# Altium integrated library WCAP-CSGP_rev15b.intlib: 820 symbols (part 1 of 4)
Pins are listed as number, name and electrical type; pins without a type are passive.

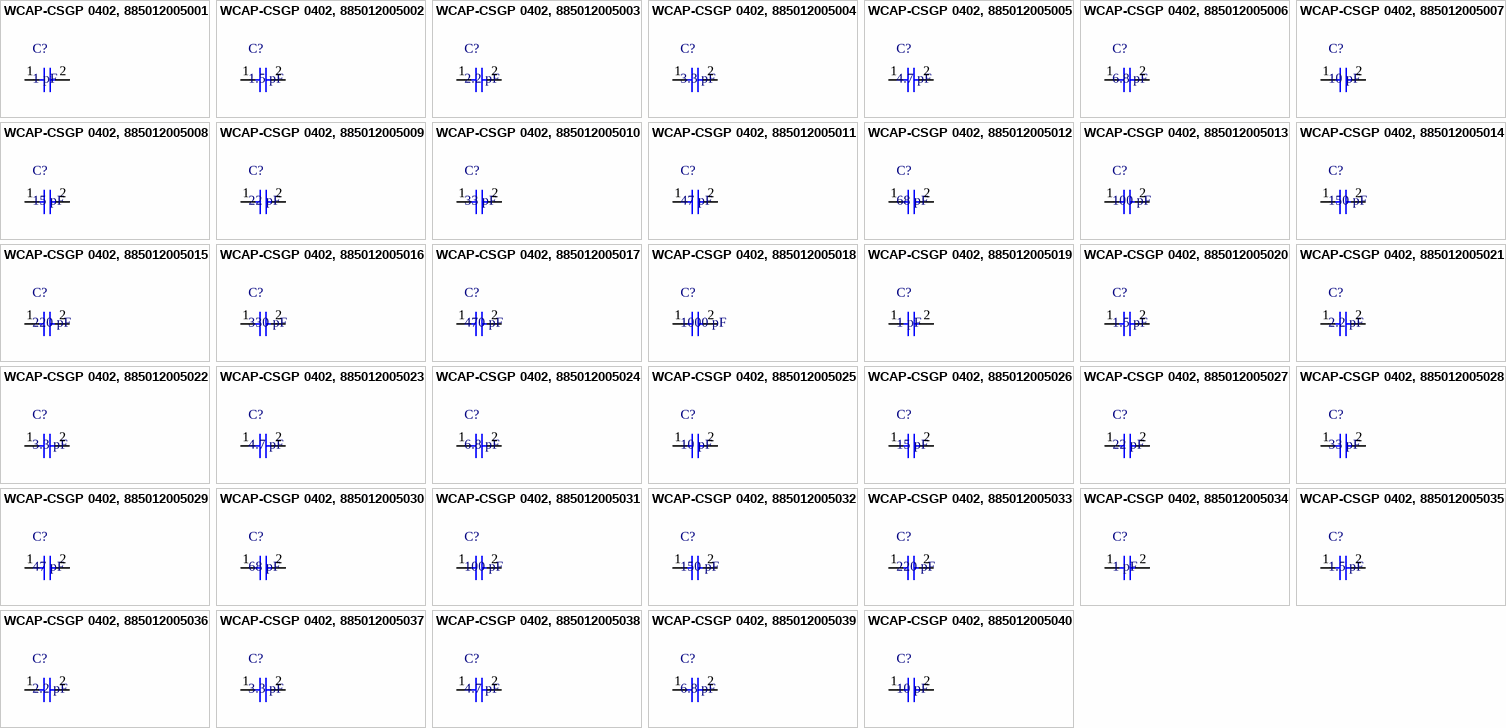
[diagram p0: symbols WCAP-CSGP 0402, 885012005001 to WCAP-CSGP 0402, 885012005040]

## WCAP-CSGP 0402, 885012005001
designator C?, comment 1 pF
WCAP-CSGP MLCC, NP0, 0402, 1 pF,10Vdc; Manufacturer: Wurth Elektronik; partNo: 885012005001; E-mail: libraries@we-online.com
footprint WCAP-CSGP 0402, H=0.5mm
pins: 1, 2

## WCAP-CSGP 0402, 885012005002
designator C?, comment 1.5 pF
WCAP-CSGP MLCC, NP0, 0402, 1.5 pF,10Vdc; Manufacturer: Wurth Elektronik; partNo: 885012005002; E-mail: libraries@we-online.com
footprint WCAP-CSGP 0402, H=0.5mm
pins: 1, 2

## WCAP-CSGP 0402, 885012005003
designator C?, comment 2.2 pF
WCAP-CSGP MLCC, NP0, 0402, 2.2 pF,10Vdc; Manufacturer: Wurth Elektronik; partNo: 885012005003; E-mail: libraries@we-online.com
footprint WCAP-CSGP 0402, H=0.5mm
pins: 1, 2

## WCAP-CSGP 0402, 885012005004
designator C?, comment 3.3 pF
WCAP-CSGP MLCC, NP0, 0402, 3.3 pF,10Vdc; Manufacturer: Wurth Elektronik; partNo: 885012005004; E-mail: libraries@we-online.com
footprint WCAP-CSGP 0402, H=0.5mm
pins: 1, 2

## WCAP-CSGP 0402, 885012005005
designator C?, comment 4.7 pF
WCAP-CSGP MLCC, NP0, 0402, 4.7 pF,10Vdc; Manufacturer: Wurth Elektronik; partNo: 885012005005; E-mail: libraries@we-online.com
footprint WCAP-CSGP 0402, H=0.5mm
pins: 1, 2

## WCAP-CSGP 0402, 885012005006
designator C?, comment 6.8 pF
WCAP-CSGP MLCC, NP0, 0402, 6.8 pF,10Vdc; Manufacturer: Wurth Elektronik; partNo: 885012005006; E-mail: libraries@we-online.com
footprint WCAP-CSGP 0402, H=0.5mm
pins: 1, 2

## WCAP-CSGP 0402, 885012005007
designator C?, comment 10 pF
WCAP-CSGP MLCC, NP0, 0402, 10 pF,10Vdc; Manufacturer: Wurth Elektronik; partNo: 885012005007; E-mail: libraries@we-online.com
footprint WCAP-CSGP 0402, H=0.5mm
pins: 1, 2

## WCAP-CSGP 0402, 885012005008
designator C?, comment 15 pF
WCAP-CSGP MLCC, NP0, 0402, 15 pF,10Vdc; Manufacturer: Wurth Elektronik; partNo: 885012005008; E-mail: libraries@we-online.com
footprint WCAP-CSGP 0402, H=0.5mm
pins: 1, 2

## WCAP-CSGP 0402, 885012005009
designator C?, comment 22 pF
WCAP-CSGP MLCC, NP0, 0402, 22 pF,10Vdc; Manufacturer: Wurth Elektronik; partNo: 885012005009; E-mail: libraries@we-online.com
footprint WCAP-CSGP 0402, H=0.5mm
pins: 1, 2

## WCAP-CSGP 0402, 885012005010
designator C?, comment 33 pF
WCAP-CSGP MLCC, NP0, 0402, 33 pF,10Vdc; Manufacturer: Wurth Elektronik; partNo: 885012005010; E-mail: libraries@we-online.com
footprint WCAP-CSGP 0402, H=0.5mm
pins: 1, 2

## WCAP-CSGP 0402, 885012005011
designator C?, comment 47 pF
WCAP-CSGP MLCC, NP0, 0402, 47 pF,10Vdc; Manufacturer: Wurth Elektronik; partNo: 885012005011; E-mail: libraries@we-online.com
footprint WCAP-CSGP 0402, H=0.5mm
pins: 1, 2

## WCAP-CSGP 0402, 885012005012
designator C?, comment 68 pF
WCAP-CSGP MLCC, NP0, 0402, 68 pF,10Vdc; Manufacturer: Wurth Elektronik; partNo: 885012005012; E-mail: libraries@we-online.com
footprint WCAP-CSGP 0402, H=0.5mm
pins: 1, 2

## WCAP-CSGP 0402, 885012005013
designator C?, comment 100 pF
WCAP-CSGP MLCC, NP0, 0402, 100 pF,10Vdc; Manufacturer: Wurth Elektronik; partNo: 885012005013; E-mail: libraries@we-online.com
footprint WCAP-CSGP 0402, H=0.5mm
pins: 1, 2

## WCAP-CSGP 0402, 885012005014
designator C?, comment 150 pF
WCAP-CSGP MLCC, NP0, 0402, 150 pF,10Vdc; Manufacturer: Wurth Elektronik; partNo: 885012005014; E-mail: libraries@we-online.com
footprint WCAP-CSGP 0402, H=0.5mm
pins: 1, 2

## WCAP-CSGP 0402, 885012005015
designator C?, comment 220 pF
WCAP-CSGP MLCC, NP0, 0402, 220 pF,10Vdc; Manufacturer: Wurth Elektronik; partNo: 885012005015; E-mail: libraries@we-online.com
footprint WCAP-CSGP 0402, H=0.5mm
pins: 1, 2

## WCAP-CSGP 0402, 885012005016
designator C?, comment 330 pF
WCAP-CSGP MLCC, NP0, 0402, 330 pF,10Vdc; Manufacturer: Wurth Elektronik; partNo: 885012005016; E-mail: libraries@we-online.com
footprint WCAP-CSGP 0402, H=0.5mm
pins: 1, 2

## WCAP-CSGP 0402, 885012005017
designator C?, comment 470 pF
WCAP-CSGP MLCC, NP0, 0402, 470 pF,10Vdc; Manufacturer: Wurth Elektronik; partNo: 885012005017; E-mail: libraries@we-online.com
footprint WCAP-CSGP 0402, H=0.5mm
pins: 1, 2

## WCAP-CSGP 0402, 885012005018
designator C?, comment 1000 pF
WCAP-CSGP MLCC, NP0, 0402, 1000 pF,10Vdc; Manufacturer: Wurth Elektronik; partNo: 885012005018; E-mail: libraries@we-online.com
footprint WCAP-CSGP 0402, H=0.5mm
pins: 1, 2

## WCAP-CSGP 0402, 885012005019
designator C?, comment 1 pF
WCAP-CSGP MLCC, NP0, 0402, 1 pF,16Vdc; Manufacturer: Wurth Elektronik; partNo: 885012005019; E-mail: libraries@we-online.com
footprint WCAP-CSGP 0402, H=0.5mm
pins: 1, 2

## WCAP-CSGP 0402, 885012005020
designator C?, comment 1.5 pF
WCAP-CSGP MLCC, NP0, 0402, 1.5 pF,16Vdc; Manufacturer: Wurth Elektronik; partNo: 885012005020; E-mail: libraries@we-online.com
footprint WCAP-CSGP 0402, H=0.5mm
pins: 1, 2

## WCAP-CSGP 0402, 885012005021
designator C?, comment 2.2 pF
WCAP-CSGP MLCC, NP0, 0402, 2.2 pF,16Vdc; Manufacturer: Wurth Elektronik; partNo: 885012005021; E-mail: libraries@we-online.com
footprint WCAP-CSGP 0402, H=0.5mm
pins: 1, 2

## WCAP-CSGP 0402, 885012005022
designator C?, comment 3.3 pF
WCAP-CSGP MLCC, NP0, 0402, 3.3 pF,16Vdc; Manufacturer: Wurth Elektronik; partNo: 885012005022; E-mail: libraries@we-online.com
footprint WCAP-CSGP 0402, H=0.5mm
pins: 1, 2

## WCAP-CSGP 0402, 885012005023
designator C?, comment 4.7 pF
WCAP-CSGP MLCC, NP0, 0402, 4.7 pF,16Vdc; Manufacturer: Wurth Elektronik; partNo: 885012005023; E-mail: libraries@we-online.com
footprint WCAP-CSGP 0402, H=0.5mm
pins: 1, 2

## WCAP-CSGP 0402, 885012005024
designator C?, comment 6.8 pF
WCAP-CSGP MLCC, NP0, 0402, 6.8 pF,16Vdc; Manufacturer: Wurth Elektronik; partNo: 885012005024; E-mail: libraries@we-online.com
footprint WCAP-CSGP 0402, H=0.5mm
pins: 1, 2

## WCAP-CSGP 0402, 885012005025
designator C?, comment 10 pF
WCAP-CSGP MLCC, NP0, 0402, 10 pF,16Vdc; Manufacturer: Wurth Elektronik; partNo: 885012005025; E-mail: libraries@we-online.com
footprint WCAP-CSGP 0402, H=0.5mm
pins: 1, 2

## WCAP-CSGP 0402, 885012005026
designator C?, comment 15 pF
WCAP-CSGP MLCC, NP0, 0402, 15 pF,16Vdc; Manufacturer: Wurth Elektronik; partNo: 885012005026; E-mail: libraries@we-online.com
footprint WCAP-CSGP 0402, H=0.5mm
pins: 1, 2

## WCAP-CSGP 0402, 885012005027
designator C?, comment 22 pF
WCAP-CSGP MLCC, NP0, 0402, 22 pF,16Vdc; Manufacturer: Wurth Elektronik; partNo: 885012005027; E-mail: libraries@we-online.com
footprint WCAP-CSGP 0402, H=0.5mm
pins: 1, 2

## WCAP-CSGP 0402, 885012005028
designator C?, comment 33 pF
WCAP-CSGP MLCC, NP0, 0402, 33 pF,16Vdc; Manufacturer: Wurth Elektronik; partNo: 885012005028; E-mail: libraries@we-online.com
footprint WCAP-CSGP 0402, H=0.5mm
pins: 1, 2

## WCAP-CSGP 0402, 885012005029
designator C?, comment 47 pF
WCAP-CSGP MLCC, NP0, 0402, 47 pF,16Vdc; Manufacturer: Wurth Elektronik; partNo: 885012005029; E-mail: libraries@we-online.com
footprint WCAP-CSGP 0402, H=0.5mm
pins: 1, 2

## WCAP-CSGP 0402, 885012005030
designator C?, comment 68 pF
WCAP-CSGP MLCC, NP0, 0402, 68 pF,16Vdc; Manufacturer: Wurth Elektronik; partNo: 885012005030; E-mail: libraries@we-online.com
footprint WCAP-CSGP 0402, H=0.5mm
pins: 1, 2

## WCAP-CSGP 0402, 885012005031
designator C?, comment 100 pF
WCAP-CSGP MLCC, NP0, 0402, 100 pF,16Vdc; Manufacturer: Wurth Elektronik; partNo: 885012005031; E-mail: libraries@we-online.com
footprint WCAP-CSGP 0402, H=0.5mm
pins: 1, 2

## WCAP-CSGP 0402, 885012005032
designator C?, comment 150 pF
WCAP-CSGP MLCC, NP0, 0402, 150 pF,16Vdc; Manufacturer: Wurth Elektronik; partNo: 885012005032; E-mail: libraries@we-online.com
footprint WCAP-CSGP 0402, H=0.5mm
pins: 1, 2

## WCAP-CSGP 0402, 885012005033
designator C?, comment 220 pF
WCAP-CSGP MLCC, NP0, 0402, 220 pF,16Vdc; Manufacturer: Wurth Elektronik; partNo: 885012005033; E-mail: libraries@we-online.com
footprint WCAP-CSGP 0402, H=0.5mm
pins: 1, 2

## WCAP-CSGP 0402, 885012005034
designator C?, comment 1 pF
WCAP-CSGP MLCC, NP0, 0402, 1 pF,25Vdc; Manufacturer: Wurth Elektronik; partNo: 885012005034; E-mail: libraries@we-online.com
footprint WCAP-CSGP 0402, H=0.5mm
pins: 1, 2

## WCAP-CSGP 0402, 885012005035
designator C?, comment 1.5 pF
WCAP-CSGP MLCC, NP0, 0402, 1.5 pF,25Vdc; Manufacturer: Wurth Elektronik; partNo: 885012005035; E-mail: libraries@we-online.com
footprint WCAP-CSGP 0402, H=0.5mm
pins: 1, 2

## WCAP-CSGP 0402, 885012005036
designator C?, comment 2.2 pF
WCAP-CSGP MLCC, NP0, 0402, 2.2 pF,25Vdc; Manufacturer: Wurth Elektronik; partNo: 885012005036; E-mail: libraries@we-online.com
footprint WCAP-CSGP 0402, H=0.5mm
pins: 1, 2

## WCAP-CSGP 0402, 885012005037
designator C?, comment 3.3 pF
WCAP-CSGP MLCC, NP0, 0402, 3.3 pF,25Vdc; Manufacturer: Wurth Elektronik; partNo: 885012005037; E-mail: libraries@we-online.com
footprint WCAP-CSGP 0402, H=0.5mm
pins: 1, 2

## WCAP-CSGP 0402, 885012005038
designator C?, comment 4.7 pF
WCAP-CSGP MLCC, NP0, 0402, 4.7 pF,25Vdc; Manufacturer: Wurth Elektronik; partNo: 885012005038; E-mail: libraries@we-online.com
footprint WCAP-CSGP 0402, H=0.5mm
pins: 1, 2

## WCAP-CSGP 0402, 885012005039
designator C?, comment 6.8 pF
WCAP-CSGP MLCC, NP0, 0402, 6.8 pF,25Vdc; Manufacturer: Wurth Elektronik; partNo: 885012005039; E-mail: libraries@we-online.com
footprint WCAP-CSGP 0402, H=0.5mm
pins: 1, 2

## WCAP-CSGP 0402, 885012005040
designator C?, comment 10 pF
WCAP-CSGP MLCC, NP0, 0402, 10 pF,25Vdc; Manufacturer: Wurth Elektronik; partNo: 885012005040; E-mail: libraries@we-online.com
footprint WCAP-CSGP 0402, H=0.5mm
pins: 1, 2

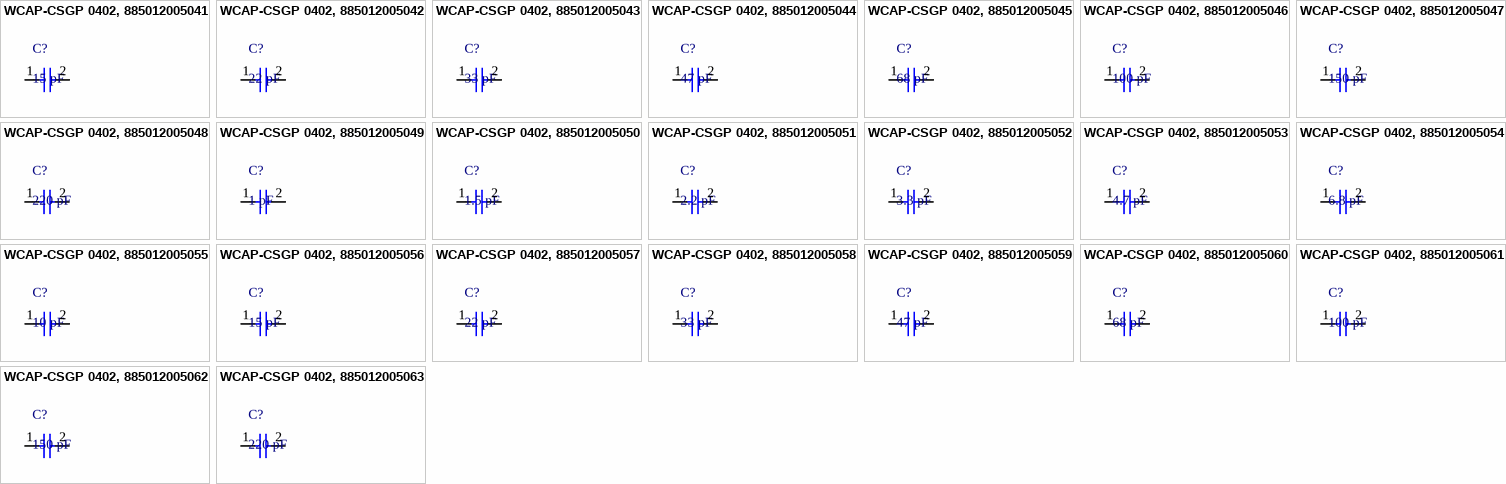
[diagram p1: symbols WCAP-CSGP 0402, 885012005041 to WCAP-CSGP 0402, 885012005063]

## WCAP-CSGP 0402, 885012005041
designator C?, comment 15 pF
WCAP-CSGP MLCC, NP0, 0402, 15 pF,25Vdc; Manufacturer: Wurth Elektronik; partNo: 885012005041; E-mail: libraries@we-online.com
footprint WCAP-CSGP 0402, H=0.5mm
pins: 1, 2

## WCAP-CSGP 0402, 885012005042
designator C?, comment 22 pF
WCAP-CSGP MLCC, NP0, 0402, 22 pF,25Vdc; Manufacturer: Wurth Elektronik; partNo: 885012005042; E-mail: libraries@we-online.com
footprint WCAP-CSGP 0402, H=0.5mm
pins: 1, 2

## WCAP-CSGP 0402, 885012005043
designator C?, comment 33 pF
WCAP-CSGP MLCC, NP0, 0402, 33 pF,25Vdc; Manufacturer: Wurth Elektronik; partNo: 885012005043; E-mail: libraries@we-online.com
footprint WCAP-CSGP 0402, H=0.5mm
pins: 1, 2

## WCAP-CSGP 0402, 885012005044
designator C?, comment 47 pF
WCAP-CSGP MLCC, NP0, 0402, 47 pF,25Vdc; Manufacturer: Wurth Elektronik; partNo: 885012005044; E-mail: libraries@we-online.com
footprint WCAP-CSGP 0402, H=0.5mm
pins: 1, 2

## WCAP-CSGP 0402, 885012005045
designator C?, comment 68 pF
WCAP-CSGP MLCC, NP0, 0402, 68 pF,25Vdc; Manufacturer: Wurth Elektronik; partNo: 885012005045; E-mail: libraries@we-online.com
footprint WCAP-CSGP 0402, H=0.5mm
pins: 1, 2

## WCAP-CSGP 0402, 885012005046
designator C?, comment 100 pF
WCAP-CSGP MLCC, NP0, 0402, 100 pF,25Vdc; Manufacturer: Wurth Elektronik; partNo: 885012005046; E-mail: libraries@we-online.com
footprint WCAP-CSGP 0402, H=0.5mm
pins: 1, 2

## WCAP-CSGP 0402, 885012005047
designator C?, comment 150 pF
WCAP-CSGP MLCC, NP0, 0402, 150 pF,25Vdc; Manufacturer: Wurth Elektronik; partNo: 885012005047; E-mail: libraries@we-online.com
footprint WCAP-CSGP 0402, H=0.5mm
pins: 1, 2

## WCAP-CSGP 0402, 885012005048
designator C?, comment 220 pF
WCAP-CSGP MLCC, NP0, 0402, 220 pF,25Vdc; Manufacturer: Wurth Elektronik; partNo: 885012005048; E-mail: libraries@we-online.com
footprint WCAP-CSGP 0402, H=0.5mm
pins: 1, 2

## WCAP-CSGP 0402, 885012005049
designator C?, comment 1 pF
WCAP-CSGP MLCC, NP0, 0402, 1 pF,50Vdc; Manufacturer: Wurth Elektronik; partNo: 885012005049; E-mail: libraries@we-online.com
footprint WCAP-CSGP 0402, H=0.5mm
pins: 1, 2

## WCAP-CSGP 0402, 885012005050
designator C?, comment 1.5 pF
WCAP-CSGP MLCC, NP0, 0402, 1.5 pF,50Vdc; Manufacturer: Wurth Elektronik; partNo: 885012005050; E-mail: libraries@we-online.com
footprint WCAP-CSGP 0402, H=0.5mm
pins: 1, 2

## WCAP-CSGP 0402, 885012005051
designator C?, comment 2.2 pF
WCAP-CSGP MLCC, NP0, 0402, 2.2 pF,50Vdc; Manufacturer: Wurth Elektronik; partNo: 885012005051; E-mail: libraries@we-online.com
footprint WCAP-CSGP 0402, H=0.5mm
pins: 1, 2

## WCAP-CSGP 0402, 885012005052
designator C?, comment 3.3 pF
WCAP-CSGP MLCC, NP0, 0402, 3.3 pF,50Vdc; Manufacturer: Wurth Elektronik; partNo: 885012005052; E-mail: libraries@we-online.com
footprint WCAP-CSGP 0402, H=0.5mm
pins: 1, 2

## WCAP-CSGP 0402, 885012005053
designator C?, comment 4.7 pF
WCAP-CSGP MLCC, NP0, 0402, 4.7 pF,50Vdc; Manufacturer: Wurth Elektronik; partNo: 885012005053; E-mail: libraries@we-online.com
footprint WCAP-CSGP 0402, H=0.5mm
pins: 1, 2

## WCAP-CSGP 0402, 885012005054
designator C?, comment 6.8 pF
WCAP-CSGP MLCC, NP0, 0402, 6.8 pF,50Vdc; Manufacturer: Wurth Elektronik; partNo: 885012005054; E-mail: libraries@we-online.com
footprint WCAP-CSGP 0402, H=0.5mm
pins: 1, 2

## WCAP-CSGP 0402, 885012005055
designator C?, comment 10 pF
WCAP-CSGP MLCC, NP0, 0402, 10 pF,50Vdc; Manufacturer: Wurth Elektronik; partNo: 885012005055; E-mail: libraries@we-online.com
footprint WCAP-CSGP 0402, H=0.5mm
pins: 1, 2

## WCAP-CSGP 0402, 885012005056
designator C?, comment 15 pF
WCAP-CSGP MLCC, NP0, 0402, 15 pF,50Vdc; Manufacturer: Wurth Elektronik; partNo: 885012005056; E-mail: libraries@we-online.com
footprint WCAP-CSGP 0402, H=0.5mm
pins: 1, 2

## WCAP-CSGP 0402, 885012005057
designator C?, comment 22 pF
WCAP-CSGP MLCC, NP0, 0402, 22 pF,50Vdc; Manufacturer: Wurth Elektronik; partNo: 885012005057; E-mail: libraries@we-online.com
footprint WCAP-CSGP 0402, H=0.5mm
pins: 1, 2

## WCAP-CSGP 0402, 885012005058
designator C?, comment 33 pF
WCAP-CSGP MLCC, NP0, 0402, 33 pF,50Vdc; Manufacturer: Wurth Elektronik; partNo: 885012005058; E-mail: libraries@we-online.com
footprint WCAP-CSGP 0402, H=0.5mm
pins: 1, 2

## WCAP-CSGP 0402, 885012005059
designator C?, comment 47 pF
WCAP-CSGP MLCC, NP0, 0402, 47 pF,50Vdc; Manufacturer: Wurth Elektronik; partNo: 885012005059; E-mail: libraries@we-online.com
footprint WCAP-CSGP 0402, H=0.5mm
pins: 1, 2

## WCAP-CSGP 0402, 885012005060
designator C?, comment 68 pF
WCAP-CSGP MLCC, NP0, 0402, 68 pF,50Vdc; Manufacturer: Wurth Elektronik; partNo: 885012005060; E-mail: libraries@we-online.com
footprint WCAP-CSGP 0402, H=0.5mm
pins: 1, 2

## WCAP-CSGP 0402, 885012005061
designator C?, comment 100 pF
WCAP-CSGP MLCC, NP0, 0402, 100 pF,50Vdc; Manufacturer: Wurth Elektronik; partNo: 885012005061; E-mail: libraries@we-online.com
footprint WCAP-CSGP 0402, H=0.5mm
pins: 1, 2

## WCAP-CSGP 0402, 885012005062
designator C?, comment 150 pF
WCAP-CSGP MLCC, NP0, 0402, 150 pF,50Vdc; Manufacturer: Wurth Elektronik; partNo: 885012005062; E-mail: libraries@we-online.com
footprint WCAP-CSGP 0402, H=0.5mm
pins: 1, 2

## WCAP-CSGP 0402, 885012005063
designator C?, comment 220 pF
WCAP-CSGP MLCC, NP0, 0402, 220 pF,50Vdc; Manufacturer: Wurth Elektronik; partNo: 885012005063; E-mail: libraries@we-online.com
footprint WCAP-CSGP 0402, H=0.5mm
pins: 1, 2


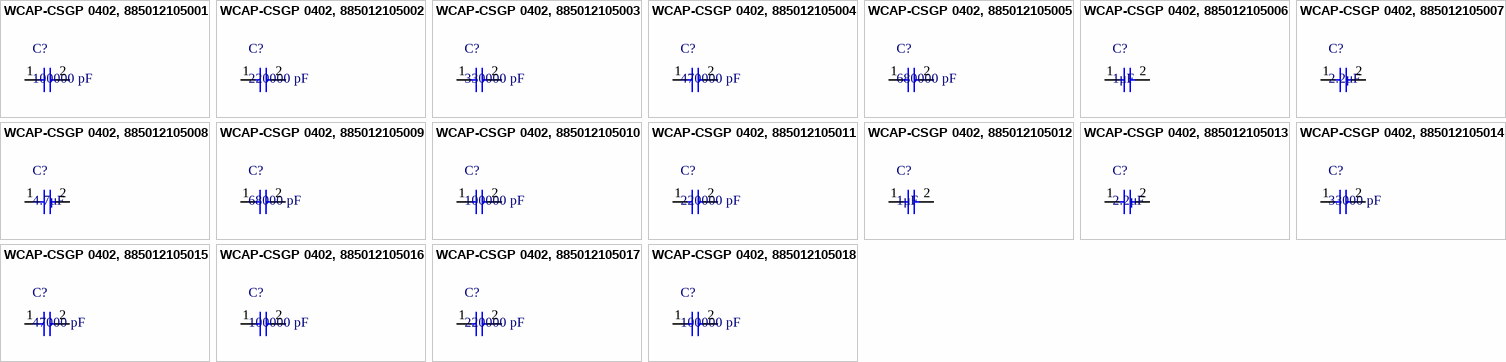
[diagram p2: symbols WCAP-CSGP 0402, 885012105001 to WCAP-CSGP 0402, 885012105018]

## WCAP-CSGP 0402, 885012105001
designator C?, comment 100000 pF
WCAP-CSGP MLCC, X5R, 0402, 100000 pF,6.3Vdc; Manufacturer: Wurth Elektronik; partNo: 885012105001; E-mail: libraries@we-online.com
footprint WCAP-CSGP 0402, H=0.5mm
pins: 1, 2

## WCAP-CSGP 0402, 885012105002
designator C?, comment 220000 pF
WCAP-CSGP MLCC, X5R, 0402, 220000 pF,6.3Vdc; Manufacturer: Wurth Elektronik; partNo: 885012105002; E-mail: libraries@we-online.com
footprint WCAP-CSGP 0402, H=0.5mm
pins: 1, 2

## WCAP-CSGP 0402, 885012105003
designator C?, comment 330000 pF
WCAP-CSGP MLCC, X5R, 0402, 330000 pF,6.3Vdc; Manufacturer: Wurth Elektronik; partNo: 885012105003; E-mail: libraries@we-online.com
footprint WCAP-CSGP 0402, H=0.5mm
pins: 1, 2

## WCAP-CSGP 0402, 885012105004
designator C?, comment 470000 pF
WCAP-CSGP MLCC, X5R, 0402, 470000 pF,6.3Vdc; Manufacturer: Wurth Elektronik; partNo: 885012105004; E-mail: libraries@we-online.com
footprint WCAP-CSGP 0402, H=0.5mm
pins: 1, 2

## WCAP-CSGP 0402, 885012105005
designator C?, comment 680000 pF
WCAP-CSGP MLCC, X5R, 0402, 680000 pF,6.3Vdc; Manufacturer: Wurth Elektronik; partNo: 885012105005; E-mail: libraries@we-online.com
footprint WCAP-CSGP 0402, H=0.5mm
pins: 1, 2

## WCAP-CSGP 0402, 885012105006
designator C?, comment 1μF
WCAP-CSGP MLCC, X5R, 0402, 1μF pF,6.3Vdc; Manufacturer: Wurth Elektronik; partNo: 885012105006; E-mail: libraries@we-online.com
footprint WCAP-CSGP 0402, H=0.5mm
pins: 1, 2

## WCAP-CSGP 0402, 885012105007
designator C?, comment 2.2μF
WCAP-CSGP MLCC, X5R, 0402, 2.2μF pF,6.3Vdc; Manufacturer: Wurth Elektronik; partNo: 885012105007; E-mail: libraries@we-online.com
footprint WCAP-CSGP 0402, H=0.5mm
pins: 1, 2

## WCAP-CSGP 0402, 885012105008
designator C?, comment 4.7μF
WCAP-CSGP MLCC, X5R, 0402, 4.7μF pF,6.3Vdc; Manufacturer: Wurth Elektronik; partNo: 885012105008; E-mail: libraries@we-online.com
footprint WCAP-CSGP 0402, H=0.5mm
pins: 1, 2

## WCAP-CSGP 0402, 885012105009
designator C?, comment 68000 pF
WCAP-CSGP MLCC, X5R, 0402, 68000 pF,10Vdc; Manufacturer: Wurth Elektronik; partNo: 885012105009; E-mail: libraries@we-online.com
footprint WCAP-CSGP 0402, H=0.5mm
pins: 1, 2

## WCAP-CSGP 0402, 885012105010
designator C?, comment 100000 pF
WCAP-CSGP MLCC, X5R, 0402, 100000 pF,10Vdc; Manufacturer: Wurth Elektronik; partNo: 885012105010; E-mail: libraries@we-online.com
footprint WCAP-CSGP 0402, H=0.5mm
pins: 1, 2

## WCAP-CSGP 0402, 885012105011
designator C?, comment 220000 pF
WCAP-CSGP MLCC, X5R, 0402, 220000 pF,10Vdc; Manufacturer: Wurth Elektronik; partNo: 885012105011; E-mail: libraries@we-online.com
footprint WCAP-CSGP 0402, H=0.5mm
pins: 1, 2

## WCAP-CSGP 0402, 885012105012
designator C?, comment 1μF
WCAP-CSGP MLCC, X5R, 0402, 1μF pF,10Vdc; Manufacturer: Wurth Elektronik; partNo: 885012105012; E-mail: libraries@we-online.com
footprint WCAP-CSGP 0402, H=0.5mm
pins: 1, 2

## WCAP-CSGP 0402, 885012105013
designator C?, comment 2.2μF
WCAP-CSGP MLCC, X5R, 0402, 2.2μF pF,10Vdc; Manufacturer: Wurth Elektronik; partNo: 885012105013; E-mail: libraries@we-online.com
footprint WCAP-CSGP 0402, H=0.5mm
pins: 1, 2

## WCAP-CSGP 0402, 885012105014
designator C?, comment 33000 pF
WCAP-CSGP MLCC, X5R, 0402, 33000 pF,16Vdc; Manufacturer: Wurth Elektronik; partNo: 885012105014; E-mail: libraries@we-online.com
footprint WCAP-CSGP 0402, H=0.5mm
pins: 1, 2

## WCAP-CSGP 0402, 885012105015
designator C?, comment 47000 pF
WCAP-CSGP MLCC, X5R, 0402, 47000 pF,16Vdc; Manufacturer: Wurth Elektronik; partNo: 885012105015; E-mail: libraries@we-online.com
footprint WCAP-CSGP 0402, H=0.5mm
pins: 1, 2

## WCAP-CSGP 0402, 885012105016
designator C?, comment 100000 pF
WCAP-CSGP MLCC, X5R, 0402, 100000 pF,16Vdc; Manufacturer: Wurth Elektronik; partNo: 885012105016; E-mail: libraries@we-online.com
footprint WCAP-CSGP 0402, H=0.5mm
pins: 1, 2

## WCAP-CSGP 0402, 885012105017
designator C?, comment 220000 pF
WCAP-CSGP MLCC, X5R, 0402, 220000 pF,16Vdc; Manufacturer: Wurth Elektronik; partNo: 885012105017; E-mail: libraries@we-online.com
footprint WCAP-CSGP 0402, H=0.5mm
pins: 1, 2

## WCAP-CSGP 0402, 885012105018
designator C?, comment 100000 pF
WCAP-CSGP MLCC, X5R, 0402, 100000 pF,25Vdc; Manufacturer: Wurth Elektronik; partNo: 885012105018; E-mail: libraries@we-online.com
footprint WCAP-CSGP 0402, H=0.5mm
pins: 1, 2


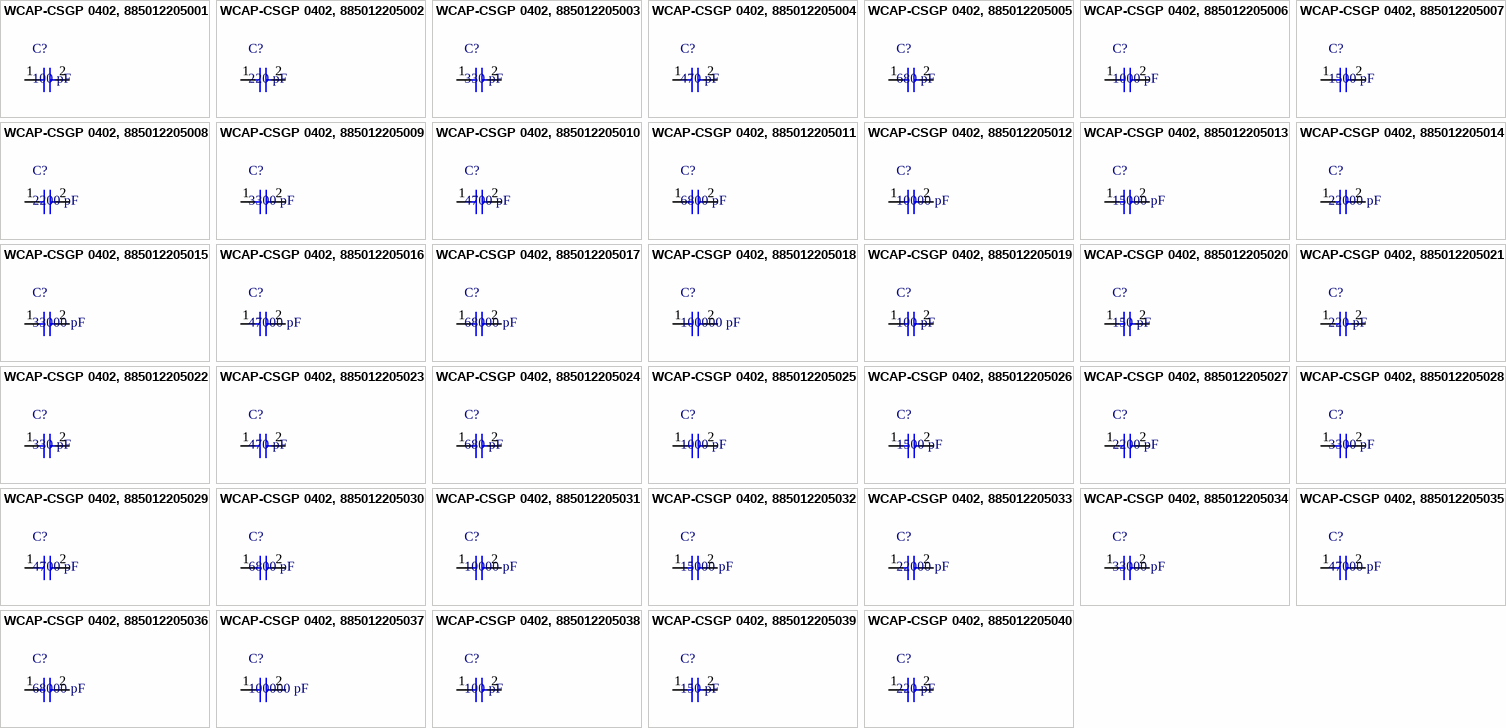
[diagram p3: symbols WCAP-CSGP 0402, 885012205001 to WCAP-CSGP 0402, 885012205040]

## WCAP-CSGP 0402, 885012205001
designator C?, comment 100 pF
WCAP-CSGP MLCC, X7R, 0402, 100 pF,10Vdc; Manufacturer: Wurth Elektronik; partNo: 885012205001; E-mail: libraries@we-online.com
footprint WCAP-CSGP 0402, H=0.5mm
pins: 1, 2

## WCAP-CSGP 0402, 885012205002
designator C?, comment 220 pF
WCAP-CSGP MLCC, X7R, 0402, 220 pF,10Vdc; Manufacturer: Wurth Elektronik; partNo: 885012205002; E-mail: libraries@we-online.com
footprint WCAP-CSGP 0402, H=0.5mm
pins: 1, 2

## WCAP-CSGP 0402, 885012205003
designator C?, comment 330 pF
WCAP-CSGP MLCC, X7R, 0402, 330 pF,10Vdc; Manufacturer: Wurth Elektronik; partNo: 885012205003; E-mail: libraries@we-online.com
footprint WCAP-CSGP 0402, H=0.5mm
pins: 1, 2

## WCAP-CSGP 0402, 885012205004
designator C?, comment 470 pF
WCAP-CSGP MLCC, X7R, 0402, 470 pF,10Vdc; Manufacturer: Wurth Elektronik; partNo: 885012205004; E-mail: libraries@we-online.com
footprint WCAP-CSGP 0402, H=0.5mm
pins: 1, 2

## WCAP-CSGP 0402, 885012205005
designator C?, comment 680 pF
WCAP-CSGP MLCC, X7R, 0402, 680 pF,10Vdc; Manufacturer: Wurth Elektronik; partNo: 885012205005; E-mail: libraries@we-online.com
footprint WCAP-CSGP 0402, H=0.5mm
pins: 1, 2

## WCAP-CSGP 0402, 885012205006
designator C?, comment 1000 pF
WCAP-CSGP MLCC, X7R, 0402, 1000 pF,10Vdc; Manufacturer: Wurth Elektronik; partNo: 885012205006; E-mail: libraries@we-online.com
footprint WCAP-CSGP 0402, H=0.5mm
pins: 1, 2

## WCAP-CSGP 0402, 885012205007
designator C?, comment 1500 pF
WCAP-CSGP MLCC, X7R, 0402, 1500 pF,10Vdc; Manufacturer: Wurth Elektronik; partNo: 885012205007; E-mail: libraries@we-online.com
footprint WCAP-CSGP 0402, H=0.5mm
pins: 1, 2

## WCAP-CSGP 0402, 885012205008
designator C?, comment 2200 pF
WCAP-CSGP MLCC, X7R, 0402, 2200 pF,10Vdc; Manufacturer: Wurth Elektronik; partNo: 885012205008; E-mail: libraries@we-online.com
footprint WCAP-CSGP 0402, H=0.5mm
pins: 1, 2

## WCAP-CSGP 0402, 885012205009
designator C?, comment 3300 pF
WCAP-CSGP MLCC, X7R, 0402, 3300 pF,10Vdc; Manufacturer: Wurth Elektronik; partNo: 885012205009; E-mail: libraries@we-online.com
footprint WCAP-CSGP 0402, H=0.5mm
pins: 1, 2

## WCAP-CSGP 0402, 885012205010
designator C?, comment 4700 pF
WCAP-CSGP MLCC, X7R, 0402, 4700 pF,10Vdc; Manufacturer: Wurth Elektronik; partNo: 885012205010; E-mail: libraries@we-online.com
footprint WCAP-CSGP 0402, H=0.5mm
pins: 1, 2

## WCAP-CSGP 0402, 885012205011
designator C?, comment 6800 pF
WCAP-CSGP MLCC, X7R, 0402, 6800 pF,10Vdc; Manufacturer: Wurth Elektronik; partNo: 885012205011; E-mail: libraries@we-online.com
footprint WCAP-CSGP 0402, H=0.5mm
pins: 1, 2

## WCAP-CSGP 0402, 885012205012
designator C?, comment 10000 pF
WCAP-CSGP MLCC, X7R, 0402, 10000 pF,10Vdc; Manufacturer: Wurth Elektronik; partNo: 885012205012; E-mail: libraries@we-online.com
footprint WCAP-CSGP 0402, H=0.5mm
pins: 1, 2

## WCAP-CSGP 0402, 885012205013
designator C?, comment 15000 pF
WCAP-CSGP MLCC, X7R, 0402, 15000 pF,10Vdc; Manufacturer: Wurth Elektronik; partNo: 885012205013; E-mail: libraries@we-online.com
footprint WCAP-CSGP 0402, H=0.5mm
pins: 1, 2

## WCAP-CSGP 0402, 885012205014
designator C?, comment 22000 pF
WCAP-CSGP MLCC, X7R, 0402, 22000 pF,10Vdc; Manufacturer: Wurth Elektronik; partNo: 885012205014; E-mail: libraries@we-online.com
footprint WCAP-CSGP 0402, H=0.5mm
pins: 1, 2

## WCAP-CSGP 0402, 885012205015
designator C?, comment 33000 pF
WCAP-CSGP MLCC, X7R, 0402, 33000 pF,10Vdc; Manufacturer: Wurth Elektronik; partNo: 885012205015; E-mail: libraries@we-online.com
footprint WCAP-CSGP 0402, H=0.5mm
pins: 1, 2

## WCAP-CSGP 0402, 885012205016
designator C?, comment 47000 pF
WCAP-CSGP MLCC, X7R, 0402, 47000 pF,10Vdc; Manufacturer: Wurth Elektronik; partNo: 885012205016; E-mail: libraries@we-online.com
footprint WCAP-CSGP 0402, H=0.5mm
pins: 1, 2

## WCAP-CSGP 0402, 885012205017
designator C?, comment 68000 pF
WCAP-CSGP MLCC, X7R, 0402, 68000 pF,10Vdc; Manufacturer: Wurth Elektronik; partNo: 885012205017; E-mail: libraries@we-online.com
footprint WCAP-CSGP 0402, H=0.5mm
pins: 1, 2

## WCAP-CSGP 0402, 885012205018
designator C?, comment 100000 pF
WCAP-CSGP MLCC, X7R, 0402, 100000 pF,10Vdc; Manufacturer: Wurth Elektronik; partNo: 885012205018; E-mail: libraries@we-online.com
footprint WCAP-CSGP 0402, H=0.5mm
pins: 1, 2

## WCAP-CSGP 0402, 885012205019
designator C?, comment 100 pF
WCAP-CSGP MLCC, X7R, 0402, 100 pF,16Vdc; Manufacturer: Wurth Elektronik; partNo: 885012205019; E-mail: libraries@we-online.com
footprint WCAP-CSGP 0402, H=0.5mm
pins: 1, 2

## WCAP-CSGP 0402, 885012205020
designator C?, comment 150 pF
WCAP-CSGP MLCC, X7R, 0402, 150 pF,16Vdc; Manufacturer: Wurth Elektronik; partNo: 885012205020; E-mail: libraries@we-online.com
footprint WCAP-CSGP 0402, H=0.5mm
pins: 1, 2

## WCAP-CSGP 0402, 885012205021
designator C?, comment 220 pF
WCAP-CSGP MLCC, X7R, 0402, 220 pF,16Vdc; Manufacturer: Wurth Elektronik; partNo: 885012205021; E-mail: libraries@we-online.com
footprint WCAP-CSGP 0402, H=0.5mm
pins: 1, 2

## WCAP-CSGP 0402, 885012205022
designator C?, comment 330 pF
WCAP-CSGP MLCC, X7R, 0402, 330 pF,16Vdc; Manufacturer: Wurth Elektronik; partNo: 885012205022; E-mail: libraries@we-online.com
footprint WCAP-CSGP 0402, H=0.5mm
pins: 1, 2

## WCAP-CSGP 0402, 885012205023
designator C?, comment 470 pF
WCAP-CSGP MLCC, X7R, 0402, 470 pF,16Vdc; Manufacturer: Wurth Elektronik; partNo: 885012205023; E-mail: libraries@we-online.com
footprint WCAP-CSGP 0402, H=0.5mm
pins: 1, 2

## WCAP-CSGP 0402, 885012205024
designator C?, comment 680 pF
WCAP-CSGP MLCC, X7R, 0402, 680 pF,16Vdc; Manufacturer: Wurth Elektronik; partNo: 885012205024; E-mail: libraries@we-online.com
footprint WCAP-CSGP 0402, H=0.5mm
pins: 1, 2

## WCAP-CSGP 0402, 885012205025
designator C?, comment 1000 pF
WCAP-CSGP MLCC, X7R, 0402, 1000 pF,16Vdc; Manufacturer: Wurth Elektronik; partNo: 885012205025; E-mail: libraries@we-online.com
footprint WCAP-CSGP 0402, H=0.5mm
pins: 1, 2

## WCAP-CSGP 0402, 885012205026
designator C?, comment 1500 pF
WCAP-CSGP MLCC, X7R, 0402, 1500 pF,16Vdc; Manufacturer: Wurth Elektronik; partNo: 885012205026; E-mail: libraries@we-online.com
footprint WCAP-CSGP 0402, H=0.5mm
pins: 1, 2

## WCAP-CSGP 0402, 885012205027
designator C?, comment 2200 pF
WCAP-CSGP MLCC, X7R, 0402, 2200 pF,16Vdc; Manufacturer: Wurth Elektronik; partNo: 885012205027; E-mail: libraries@we-online.com
footprint WCAP-CSGP 0402, H=0.5mm
pins: 1, 2

## WCAP-CSGP 0402, 885012205028
designator C?, comment 3300 pF
WCAP-CSGP MLCC, X7R, 0402, 3300 pF,16Vdc; Manufacturer: Wurth Elektronik; partNo: 885012205028; E-mail: libraries@we-online.com
footprint WCAP-CSGP 0402, H=0.5mm
pins: 1, 2

## WCAP-CSGP 0402, 885012205029
designator C?, comment 4700 pF
WCAP-CSGP MLCC, X7R, 0402, 4700 pF,16Vdc; Manufacturer: Wurth Elektronik; partNo: 885012205029; E-mail: libraries@we-online.com
footprint WCAP-CSGP 0402, H=0.5mm
pins: 1, 2

## WCAP-CSGP 0402, 885012205030
designator C?, comment 6800 pF
WCAP-CSGP MLCC, X7R, 0402, 6800 pF,16Vdc; Manufacturer: Wurth Elektronik; partNo: 885012205030; E-mail: libraries@we-online.com
footprint WCAP-CSGP 0402, H=0.5mm
pins: 1, 2

## WCAP-CSGP 0402, 885012205031
designator C?, comment 10000 pF
WCAP-CSGP MLCC, X7R, 0402, 10000 pF,16Vdc; Manufacturer: Wurth Elektronik; partNo: 885012205031; E-mail: libraries@we-online.com
footprint WCAP-CSGP 0402, H=0.5mm
pins: 1, 2

## WCAP-CSGP 0402, 885012205032
designator C?, comment 15000 pF
WCAP-CSGP MLCC, X7R, 0402, 15000 pF,16Vdc; Manufacturer: Wurth Elektronik; partNo: 885012205032; E-mail: libraries@we-online.com
footprint WCAP-CSGP 0402, H=0.5mm
pins: 1, 2

## WCAP-CSGP 0402, 885012205033
designator C?, comment 22000 pF
WCAP-CSGP MLCC, X7R, 0402, 22000 pF,16Vdc; Manufacturer: Wurth Elektronik; partNo: 885012205033; E-mail: libraries@we-online.com
footprint WCAP-CSGP 0402, H=0.5mm
pins: 1, 2

## WCAP-CSGP 0402, 885012205034
designator C?, comment 33000 pF
WCAP-CSGP MLCC, X7R, 0402, 33000 pF,16Vdc; Manufacturer: Wurth Elektronik; partNo: 885012205034; E-mail: libraries@we-online.com
footprint WCAP-CSGP 0402, H=0.5mm
pins: 1, 2

## WCAP-CSGP 0402, 885012205035
designator C?, comment 47000 pF
WCAP-CSGP MLCC, X7R, 0402, 47000 pF,16Vdc; Manufacturer: Wurth Elektronik; partNo: 885012205035; E-mail: libraries@we-online.com
footprint WCAP-CSGP 0402, H=0.5mm
pins: 1, 2

## WCAP-CSGP 0402, 885012205036
designator C?, comment 68000 pF
WCAP-CSGP MLCC, X7R, 0402, 68000 pF,16Vdc; Manufacturer: Wurth Elektronik; partNo: 885012205036; E-mail: libraries@we-online.com
footprint WCAP-CSGP 0402, H=0.5mm
pins: 1, 2

## WCAP-CSGP 0402, 885012205037
designator C?, comment 100000 pF
WCAP-CSGP MLCC, X7R, 0402, 100000 pF,16Vdc; Manufacturer: Wurth Elektronik; partNo: 885012205037; E-mail: libraries@we-online.com
footprint WCAP-CSGP 0402, H=0.5mm
pins: 1, 2

## WCAP-CSGP 0402, 885012205038
designator C?, comment 100 pF
WCAP-CSGP MLCC, X7R, 0402, 100 pF,25Vdc; Manufacturer: Wurth Elektronik; partNo: 885012205038; E-mail: libraries@we-online.com
footprint WCAP-CSGP 0402, H=0.5mm
pins: 1, 2

## WCAP-CSGP 0402, 885012205039
designator C?, comment 150 pF
WCAP-CSGP MLCC, X7R, 0402, 150 pF,25Vdc; Manufacturer: Wurth Elektronik; partNo: 885012205039; E-mail: libraries@we-online.com
footprint WCAP-CSGP 0402, H=0.5mm
pins: 1, 2

## WCAP-CSGP 0402, 885012205040
designator C?, comment 220 pF
WCAP-CSGP MLCC, X7R, 0402, 220 pF,25Vdc; Manufacturer: Wurth Elektronik; partNo: 885012205040; E-mail: libraries@we-online.com
footprint WCAP-CSGP 0402, H=0.5mm
pins: 1, 2

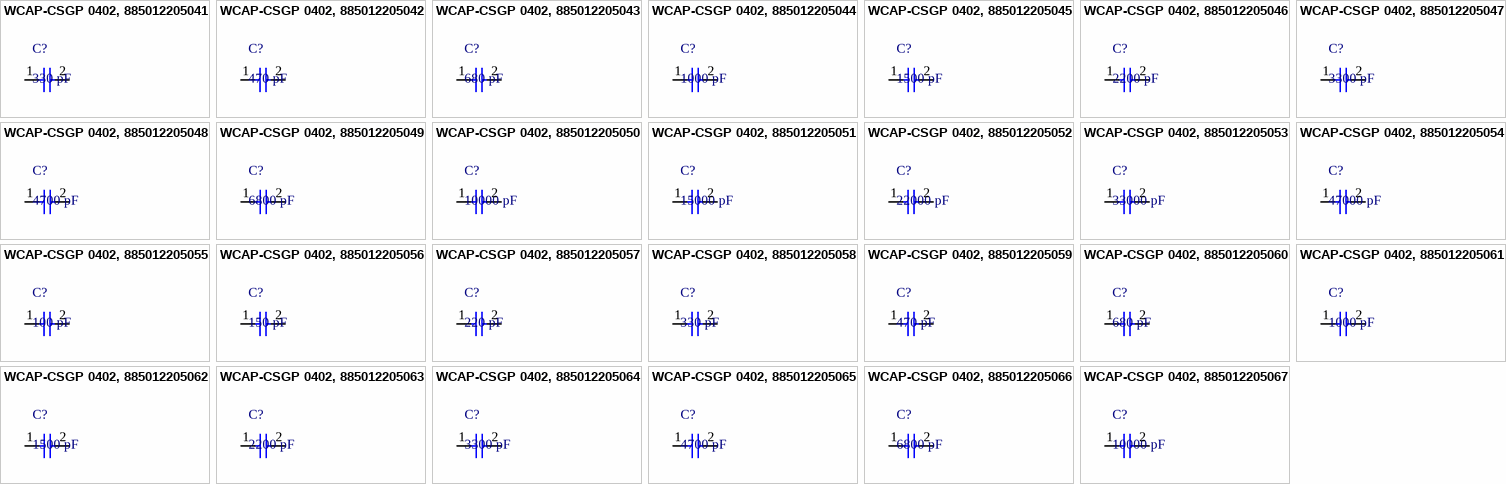
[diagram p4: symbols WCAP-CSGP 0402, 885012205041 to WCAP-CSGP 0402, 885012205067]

## WCAP-CSGP 0402, 885012205041
designator C?, comment 330 pF
WCAP-CSGP MLCC, X7R, 0402, 330 pF,25Vdc; Manufacturer: Wurth Elektronik; partNo: 885012205041; E-mail: libraries@we-online.com
footprint WCAP-CSGP 0402, H=0.5mm
pins: 1, 2

## WCAP-CSGP 0402, 885012205042
designator C?, comment 470 pF
WCAP-CSGP MLCC, X7R, 0402, 470 pF,25Vdc; Manufacturer: Wurth Elektronik; partNo: 885012205042; E-mail: libraries@we-online.com
footprint WCAP-CSGP 0402, H=0.5mm
pins: 1, 2

## WCAP-CSGP 0402, 885012205043
designator C?, comment 680 pF
WCAP-CSGP MLCC, X7R, 0402, 680 pF,25Vdc; Manufacturer: Wurth Elektronik; partNo: 885012205043; E-mail: libraries@we-online.com
footprint WCAP-CSGP 0402, H=0.5mm
pins: 1, 2

## WCAP-CSGP 0402, 885012205044
designator C?, comment 1000 pF
WCAP-CSGP MLCC, X7R, 0402, 1000 pF,25Vdc; Manufacturer: Wurth Elektronik; partNo: 885012205044; E-mail: libraries@we-online.com
footprint WCAP-CSGP 0402, H=0.5mm
pins: 1, 2

## WCAP-CSGP 0402, 885012205045
designator C?, comment 1500 pF
WCAP-CSGP MLCC, X7R, 0402, 1500 pF,25Vdc; Manufacturer: Wurth Elektronik; partNo: 885012205045; E-mail: libraries@we-online.com
footprint WCAP-CSGP 0402, H=0.5mm
pins: 1, 2

## WCAP-CSGP 0402, 885012205046
designator C?, comment 2200 pF
WCAP-CSGP MLCC, X7R, 0402, 2200 pF,25Vdc; Manufacturer: Wurth Elektronik; partNo: 885012205046; E-mail: libraries@we-online.com
footprint WCAP-CSGP 0402, H=0.5mm
pins: 1, 2

## WCAP-CSGP 0402, 885012205047
designator C?, comment 3300 pF
WCAP-CSGP MLCC, X7R, 0402, 3300 pF,25Vdc; Manufacturer: Wurth Elektronik; partNo: 885012205047; E-mail: libraries@we-online.com
footprint WCAP-CSGP 0402, H=0.5mm
pins: 1, 2

## WCAP-CSGP 0402, 885012205048
designator C?, comment 4700 pF
WCAP-CSGP MLCC, X7R, 0402, 4700 pF,25Vdc; Manufacturer: Wurth Elektronik; partNo: 885012205048; E-mail: libraries@we-online.com
footprint WCAP-CSGP 0402, H=0.5mm
pins: 1, 2

## WCAP-CSGP 0402, 885012205049
designator C?, comment 6800 pF
WCAP-CSGP MLCC, X7R, 0402, 6800 pF,25Vdc; Manufacturer: Wurth Elektronik; partNo: 885012205049; E-mail: libraries@we-online.com
footprint WCAP-CSGP 0402, H=0.5mm
pins: 1, 2

## WCAP-CSGP 0402, 885012205050
designator C?, comment 10000 pF
WCAP-CSGP MLCC, X7R, 0402, 10000 pF,25Vdc; Manufacturer: Wurth Elektronik; partNo: 885012205050; E-mail: libraries@we-online.com
footprint WCAP-CSGP 0402, H=0.5mm
pins: 1, 2

## WCAP-CSGP 0402, 885012205051
designator C?, comment 15000 pF
WCAP-CSGP MLCC, X7R, 0402, 15000 pF,25Vdc; Manufacturer: Wurth Elektronik; partNo: 885012205051; E-mail: libraries@we-online.com
footprint WCAP-CSGP 0402, H=0.5mm
pins: 1, 2

## WCAP-CSGP 0402, 885012205052
designator C?, comment 22000 pF
WCAP-CSGP MLCC, X7R, 0402, 22000 pF,25Vdc; Manufacturer: Wurth Elektronik; partNo: 885012205052; E-mail: libraries@we-online.com
footprint WCAP-CSGP 0402, H=0.5mm
pins: 1, 2

## WCAP-CSGP 0402, 885012205053
designator C?, comment 33000 pF
WCAP-CSGP MLCC, X7R, 0402, 33000 pF,25Vdc; Manufacturer: Wurth Elektronik; partNo: 885012205053; E-mail: libraries@we-online.com
footprint WCAP-CSGP 0402, H=0.5mm
pins: 1, 2

## WCAP-CSGP 0402, 885012205054
designator C?, comment 47000 pF
WCAP-CSGP MLCC, X7R, 0402, 47000 pF,25Vdc; Manufacturer: Wurth Elektronik; partNo: 885012205054; E-mail: libraries@we-online.com
footprint WCAP-CSGP 0402, H=0.5mm
pins: 1, 2

## WCAP-CSGP 0402, 885012205055
designator C?, comment 100 pF
WCAP-CSGP MLCC, X7R, 0402, 100 pF,50Vdc; Manufacturer: Wurth Elektronik; partNo: 885012205055; E-mail: libraries@we-online.com
footprint WCAP-CSGP 0402, H=0.5mm
pins: 1, 2

## WCAP-CSGP 0402, 885012205056
designator C?, comment 150 pF
WCAP-CSGP MLCC, X7R, 0402, 150 pF,50Vdc; Manufacturer: Wurth Elektronik; partNo: 885012205056; E-mail: libraries@we-online.com
footprint WCAP-CSGP 0402, H=0.5mm
pins: 1, 2

## WCAP-CSGP 0402, 885012205057
designator C?, comment 220 pF
WCAP-CSGP MLCC, X7R, 0402, 220 pF,50Vdc; Manufacturer: Wurth Elektronik; partNo: 885012205057; E-mail: libraries@we-online.com
footprint WCAP-CSGP 0402, H=0.5mm
pins: 1, 2

## WCAP-CSGP 0402, 885012205058
designator C?, comment 330 pF
WCAP-CSGP MLCC, X7R, 0402, 330 pF,50Vdc; Manufacturer: Wurth Elektronik; partNo: 885012205058; E-mail: libraries@we-online.com
footprint WCAP-CSGP 0402, H=0.5mm
pins: 1, 2

## WCAP-CSGP 0402, 885012205059
designator C?, comment 470 pF
WCAP-CSGP MLCC, X7R, 0402, 470 pF,50Vdc; Manufacturer: Wurth Elektronik; partNo: 885012205059; E-mail: libraries@we-online.com
footprint WCAP-CSGP 0402, H=0.5mm
pins: 1, 2

## WCAP-CSGP 0402, 885012205060
designator C?, comment 680 pF
WCAP-CSGP MLCC, X7R, 0402, 680 pF,50Vdc; Manufacturer: Wurth Elektronik; partNo: 885012205060; E-mail: libraries@we-online.com
footprint WCAP-CSGP 0402, H=0.5mm
pins: 1, 2

## WCAP-CSGP 0402, 885012205061
designator C?, comment 1000 pF
WCAP-CSGP MLCC, X7R, 0402, 1000 pF,50Vdc; Manufacturer: Wurth Elektronik; partNo: 885012205061; E-mail: libraries@we-online.com
footprint WCAP-CSGP 0402, H=0.5mm
pins: 1, 2

## WCAP-CSGP 0402, 885012205062
designator C?, comment 1500 pF
WCAP-CSGP MLCC, X7R, 0402, 1500 pF,50Vdc; Manufacturer: Wurth Elektronik; partNo: 885012205062; E-mail: libraries@we-online.com
footprint WCAP-CSGP 0402, H=0.5mm
pins: 1, 2

## WCAP-CSGP 0402, 885012205063
designator C?, comment 2200 pF
WCAP-CSGP MLCC, X7R, 0402, 2200 pF,50Vdc; Manufacturer: Wurth Elektronik; partNo: 885012205063; E-mail: libraries@we-online.com
footprint WCAP-CSGP 0402, H=0.5mm
pins: 1, 2

## WCAP-CSGP 0402, 885012205064
designator C?, comment 3300 pF
WCAP-CSGP MLCC, X7R, 0402, 3300 pF,50Vdc; Manufacturer: Wurth Elektronik; partNo: 885012205064; E-mail: libraries@we-online.com
footprint WCAP-CSGP 0402, H=0.5mm
pins: 1, 2

## WCAP-CSGP 0402, 885012205065
designator C?, comment 4700 pF
WCAP-CSGP MLCC, X7R, 0402, 4700 pF,50Vdc; Manufacturer: Wurth Elektronik; partNo: 885012205065; E-mail: libraries@we-online.com
footprint WCAP-CSGP 0402, H=0.5mm
pins: 1, 2

## WCAP-CSGP 0402, 885012205066
designator C?, comment 6800 pF
WCAP-CSGP MLCC, X7R, 0402, 6800 pF,50Vdc; Manufacturer: Wurth Elektronik; partNo: 885012205066; E-mail: libraries@we-online.com
footprint WCAP-CSGP 0402, H=0.5mm
pins: 1, 2

## WCAP-CSGP 0402, 885012205067
designator C?, comment 10000 pF
WCAP-CSGP MLCC, X7R, 0402, 10000 pF,50Vdc; Manufacturer: Wurth Elektronik; partNo: 885012205067; E-mail: libraries@we-online.com
footprint WCAP-CSGP 0402, H=0.5mm
pins: 1, 2


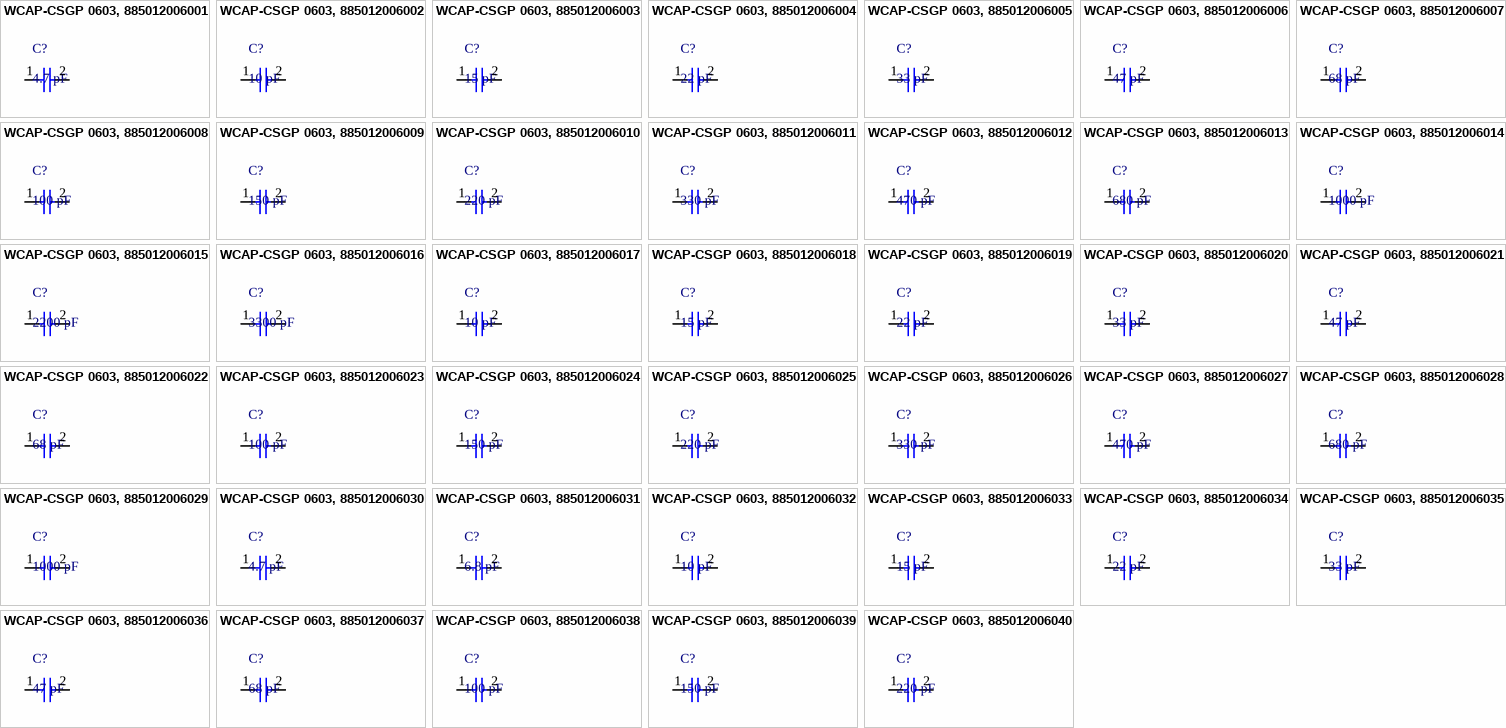
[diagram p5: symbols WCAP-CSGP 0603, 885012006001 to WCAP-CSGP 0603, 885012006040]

## WCAP-CSGP 0603, 885012006001
designator C?, comment 4.7 pF
WCAP-CSGP MLCC, NP0, 0603, 4.7 pF,10Vdc; Manufacturer: Wurth Elektronik; partNo: 885012006001; E-mail: libraries@we-online.com
footprint WCAP-CSGP 0603, H=0.8mm
pins: 1, 2

## WCAP-CSGP 0603, 885012006002
designator C?, comment 10 pF
WCAP-CSGP MLCC, NP0, 0603, 10 pF,10Vdc; Manufacturer: Wurth Elektronik; partNo: 885012006002; E-mail: libraries@we-online.com
footprint WCAP-CSGP 0603, H=0.8mm
pins: 1, 2

## WCAP-CSGP 0603, 885012006003
designator C?, comment 15 pF
WCAP-CSGP MLCC, NP0, 0603, 15 pF,10Vdc; Manufacturer: Wurth Elektronik; partNo: 885012006003; E-mail: libraries@we-online.com
footprint WCAP-CSGP 0603, H=0.8mm
pins: 1, 2

## WCAP-CSGP 0603, 885012006004
designator C?, comment 22 pF
WCAP-CSGP MLCC, NP0, 0603, 22 pF,10Vdc; Manufacturer: Wurth Elektronik; partNo: 885012006004; E-mail: libraries@we-online.com
footprint WCAP-CSGP 0603, H=0.8mm
pins: 1, 2

## WCAP-CSGP 0603, 885012006005
designator C?, comment 33 pF
WCAP-CSGP MLCC, NP0, 0603, 33 pF,10Vdc; Manufacturer: Wurth Elektronik; partNo: 885012006005; E-mail: libraries@we-online.com
footprint WCAP-CSGP 0603, H=0.8mm
pins: 1, 2

## WCAP-CSGP 0603, 885012006006
designator C?, comment 47 pF
WCAP-CSGP MLCC, NP0, 0603, 47 pF,10Vdc; Manufacturer: Wurth Elektronik; partNo: 885012006006; E-mail: libraries@we-online.com
footprint WCAP-CSGP 0603, H=0.8mm
pins: 1, 2

## WCAP-CSGP 0603, 885012006007
designator C?, comment 68 pF
WCAP-CSGP MLCC, NP0, 0603, 68 pF,10Vdc; Manufacturer: Wurth Elektronik; partNo: 885012006007; E-mail: libraries@we-online.com
footprint WCAP-CSGP 0603, H=0.8mm
pins: 1, 2

## WCAP-CSGP 0603, 885012006008
designator C?, comment 100 pF
WCAP-CSGP MLCC, NP0, 0603, 100 pF,10Vdc; Manufacturer: Wurth Elektronik; partNo: 885012006008; E-mail: libraries@we-online.com
footprint WCAP-CSGP 0603, H=0.8mm
pins: 1, 2

## WCAP-CSGP 0603, 885012006009
designator C?, comment 150 pF
WCAP-CSGP MLCC, NP0, 0603, 150 pF,10Vdc; Manufacturer: Wurth Elektronik; partNo: 885012006009; E-mail: libraries@we-online.com
footprint WCAP-CSGP 0603, H=0.8mm
pins: 1, 2

## WCAP-CSGP 0603, 885012006010
designator C?, comment 220 pF
WCAP-CSGP MLCC, NP0, 0603, 220 pF,10Vdc; Manufacturer: Wurth Elektronik; partNo: 885012006010; E-mail: libraries@we-online.com
footprint WCAP-CSGP 0603, H=0.8mm
pins: 1, 2

## WCAP-CSGP 0603, 885012006011
designator C?, comment 330 pF
WCAP-CSGP MLCC, NP0, 0603, 330 pF,10Vdc; Manufacturer: Wurth Elektronik; partNo: 885012006011; E-mail: libraries@we-online.com
footprint WCAP-CSGP 0603, H=0.8mm
pins: 1, 2

## WCAP-CSGP 0603, 885012006012
designator C?, comment 470 pF
WCAP-CSGP MLCC, NP0, 0603, 470 pF,10Vdc; Manufacturer: Wurth Elektronik; partNo: 885012006012; E-mail: libraries@we-online.com
footprint WCAP-CSGP 0603, H=0.8mm
pins: 1, 2

## WCAP-CSGP 0603, 885012006013
designator C?, comment 680 pF
WCAP-CSGP MLCC, NP0, 0603, 680 pF,10Vdc; Manufacturer: Wurth Elektronik; partNo: 885012006013; E-mail: libraries@we-online.com
footprint WCAP-CSGP 0603, H=0.8mm
pins: 1, 2

## WCAP-CSGP 0603, 885012006014
designator C?, comment 1000 pF
WCAP-CSGP MLCC, NP0, 0603, 1000 pF,10Vdc; Manufacturer: Wurth Elektronik; partNo: 885012006014; E-mail: libraries@we-online.com
footprint WCAP-CSGP 0603, H=0.8mm
pins: 1, 2

## WCAP-CSGP 0603, 885012006015
designator C?, comment 2200 pF
WCAP-CSGP MLCC, NP0, 0603, 2200 pF,10Vdc; Manufacturer: Wurth Elektronik; partNo: 885012006015; E-mail: libraries@we-online.com
footprint WCAP-CSGP 0603, H=0.8mm
pins: 1, 2

## WCAP-CSGP 0603, 885012006016
designator C?, comment 3300 pF
WCAP-CSGP MLCC, NP0, 0603, 3300 pF,10Vdc; Manufacturer: Wurth Elektronik; partNo: 885012006016; E-mail: libraries@we-online.com
footprint WCAP-CSGP 0603, H=0.8mm
pins: 1, 2

## WCAP-CSGP 0603, 885012006017
designator C?, comment 10 pF
WCAP-CSGP MLCC, NP0, 0603, 10 pF,16Vdc; Manufacturer: Wurth Elektronik; partNo: 885012006017; E-mail: libraries@we-online.com
footprint WCAP-CSGP 0603, H=0.8mm
pins: 1, 2

## WCAP-CSGP 0603, 885012006018
designator C?, comment 15 pF
WCAP-CSGP MLCC, NP0, 0603, 15 pF,16Vdc; Manufacturer: Wurth Elektronik; partNo: 885012006018; E-mail: libraries@we-online.com
footprint WCAP-CSGP 0603, H=0.8mm
pins: 1, 2

## WCAP-CSGP 0603, 885012006019
designator C?, comment 22 pF
WCAP-CSGP MLCC, NP0, 0603, 22 pF,16Vdc; Manufacturer: Wurth Elektronik; partNo: 885012006019; E-mail: libraries@we-online.com
footprint WCAP-CSGP 0603, H=0.8mm
pins: 1, 2

## WCAP-CSGP 0603, 885012006020
designator C?, comment 33 pF
WCAP-CSGP MLCC, NP0, 0603, 33 pF,16Vdc; Manufacturer: Wurth Elektronik; partNo: 885012006020; E-mail: libraries@we-online.com
footprint WCAP-CSGP 0603, H=0.8mm
pins: 1, 2

## WCAP-CSGP 0603, 885012006021
designator C?, comment 47 pF
WCAP-CSGP MLCC, NP0, 0603, 47 pF,16Vdc; Manufacturer: Wurth Elektronik; partNo: 885012006021; E-mail: libraries@we-online.com
footprint WCAP-CSGP 0603, H=0.8mm
pins: 1, 2

## WCAP-CSGP 0603, 885012006022
designator C?, comment 68 pF
WCAP-CSGP MLCC, NP0, 0603, 68 pF,16Vdc; Manufacturer: Wurth Elektronik; partNo: 885012006022; E-mail: libraries@we-online.com
footprint WCAP-CSGP 0603, H=0.8mm
pins: 1, 2

## WCAP-CSGP 0603, 885012006023
designator C?, comment 100 pF
WCAP-CSGP MLCC, NP0, 0603, 100 pF,16Vdc; Manufacturer: Wurth Elektronik; partNo: 885012006023; E-mail: libraries@we-online.com
footprint WCAP-CSGP 0603, H=0.8mm
pins: 1, 2

## WCAP-CSGP 0603, 885012006024
designator C?, comment 150 pF
WCAP-CSGP MLCC, NP0, 0603, 150 pF,16Vdc; Manufacturer: Wurth Elektronik; partNo: 885012006024; E-mail: libraries@we-online.com
footprint WCAP-CSGP 0603, H=0.8mm
pins: 1, 2

## WCAP-CSGP 0603, 885012006025
designator C?, comment 220 pF
WCAP-CSGP MLCC, NP0, 0603, 220 pF,16Vdc; Manufacturer: Wurth Elektronik; partNo: 885012006025; E-mail: libraries@we-online.com
footprint WCAP-CSGP 0603, H=0.8mm
pins: 1, 2

## WCAP-CSGP 0603, 885012006026
designator C?, comment 330 pF
WCAP-CSGP MLCC, NP0, 0603, 330 pF,16Vdc; Manufacturer: Wurth Elektronik; partNo: 885012006026; E-mail: libraries@we-online.com
footprint WCAP-CSGP 0603, H=0.8mm
pins: 1, 2

## WCAP-CSGP 0603, 885012006027
designator C?, comment 470 pF
WCAP-CSGP MLCC, NP0, 0603, 470 pF,16Vdc; Manufacturer: Wurth Elektronik; partNo: 885012006027; E-mail: libraries@we-online.com
footprint WCAP-CSGP 0603, H=0.8mm
pins: 1, 2

## WCAP-CSGP 0603, 885012006028
designator C?, comment 680 pF
WCAP-CSGP MLCC, NP0, 0603, 680 pF,16Vdc; Manufacturer: Wurth Elektronik; partNo: 885012006028; E-mail: libraries@we-online.com
footprint WCAP-CSGP 0603, H=0.8mm
pins: 1, 2

## WCAP-CSGP 0603, 885012006029
designator C?, comment 1000 pF
WCAP-CSGP MLCC, NP0, 0603, 1000 pF,16Vdc; Manufacturer: Wurth Elektronik; partNo: 885012006029; E-mail: libraries@we-online.com
footprint WCAP-CSGP 0603, H=0.8mm
pins: 1, 2

## WCAP-CSGP 0603, 885012006030
designator C?, comment 4.7 pF
WCAP-CSGP MLCC, NP0, 0603, 4.7 pF,25Vdc; Manufacturer: Wurth Elektronik; partNo: 885012006030; E-mail: libraries@we-online.com
footprint WCAP-CSGP 0603, H=0.8mm
pins: 1, 2

## WCAP-CSGP 0603, 885012006031
designator C?, comment 6.8 pF
WCAP-CSGP MLCC, NP0, 0603, 6.8 pF,25Vdc; Manufacturer: Wurth Elektronik; partNo: 885012006031; E-mail: libraries@we-online.com
footprint WCAP-CSGP 0603, H=0.8mm
pins: 1, 2

## WCAP-CSGP 0603, 885012006032
designator C?, comment 10 pF
WCAP-CSGP MLCC, NP0, 0603, 10 pF,25Vdc; Manufacturer: Wurth Elektronik; partNo: 885012006032; E-mail: libraries@we-online.com
footprint WCAP-CSGP 0603, H=0.8mm
pins: 1, 2

## WCAP-CSGP 0603, 885012006033
designator C?, comment 15 pF
WCAP-CSGP MLCC, NP0, 0603, 15 pF,25Vdc; Manufacturer: Wurth Elektronik; partNo: 885012006033; E-mail: libraries@we-online.com
footprint WCAP-CSGP 0603, H=0.8mm
pins: 1, 2

## WCAP-CSGP 0603, 885012006034
designator C?, comment 22 pF
WCAP-CSGP MLCC, NP0, 0603, 22 pF,25Vdc; Manufacturer: Wurth Elektronik; partNo: 885012006034; E-mail: libraries@we-online.com
footprint WCAP-CSGP 0603, H=0.8mm
pins: 1, 2

## WCAP-CSGP 0603, 885012006035
designator C?, comment 33 pF
WCAP-CSGP MLCC, NP0, 0603, 33 pF,25Vdc; Manufacturer: Wurth Elektronik; partNo: 885012006035; E-mail: libraries@we-online.com
footprint WCAP-CSGP 0603, H=0.8mm
pins: 1, 2

## WCAP-CSGP 0603, 885012006036
designator C?, comment 47 pF
WCAP-CSGP MLCC, NP0, 0603, 47 pF,25Vdc; Manufacturer: Wurth Elektronik; partNo: 885012006036; E-mail: libraries@we-online.com
footprint WCAP-CSGP 0603, H=0.8mm
pins: 1, 2

## WCAP-CSGP 0603, 885012006037
designator C?, comment 68 pF
WCAP-CSGP MLCC, NP0, 0603, 68 pF,25Vdc; Manufacturer: Wurth Elektronik; partNo: 885012006037; E-mail: libraries@we-online.com
footprint WCAP-CSGP 0603, H=0.8mm
pins: 1, 2

## WCAP-CSGP 0603, 885012006038
designator C?, comment 100 pF
WCAP-CSGP MLCC, NP0, 0603, 100 pF,25Vdc; Manufacturer: Wurth Elektronik; partNo: 885012006038; E-mail: libraries@we-online.com
footprint WCAP-CSGP 0603, H=0.8mm
pins: 1, 2

## WCAP-CSGP 0603, 885012006039
designator C?, comment 150 pF
WCAP-CSGP MLCC, NP0, 0603, 150 pF,25Vdc; Manufacturer: Wurth Elektronik; partNo: 885012006039; E-mail: libraries@we-online.com
footprint WCAP-CSGP 0603, H=0.8mm
pins: 1, 2

## WCAP-CSGP 0603, 885012006040
designator C?, comment 220 pF
WCAP-CSGP MLCC, NP0, 0603, 220 pF,25Vdc; Manufacturer: Wurth Elektronik; partNo: 885012006040; E-mail: libraries@we-online.com
footprint WCAP-CSGP 0603, H=0.8mm
pins: 1, 2

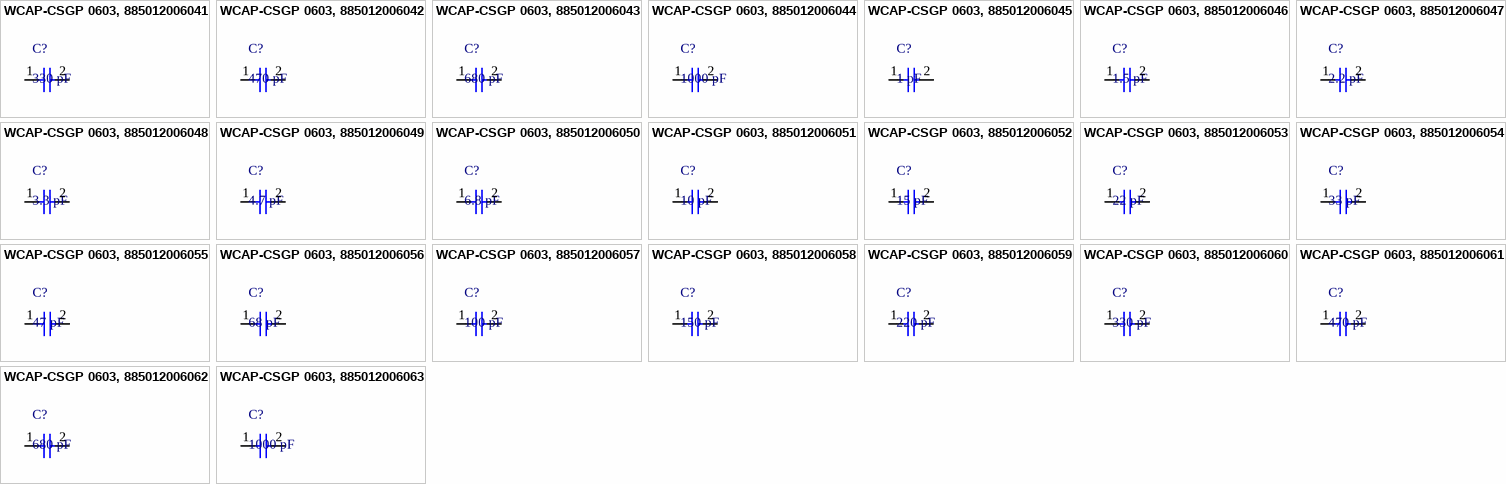
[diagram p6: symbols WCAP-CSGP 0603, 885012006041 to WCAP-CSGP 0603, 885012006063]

## WCAP-CSGP 0603, 885012006041
designator C?, comment 330 pF
WCAP-CSGP MLCC, NP0, 0603, 330 pF,25Vdc; Manufacturer: Wurth Elektronik; partNo: 885012006041; E-mail: libraries@we-online.com
footprint WCAP-CSGP 0603, H=0.8mm
pins: 1, 2

## WCAP-CSGP 0603, 885012006042
designator C?, comment 470 pF
WCAP-CSGP MLCC, NP0, 0603, 470 pF,25Vdc; Manufacturer: Wurth Elektronik; partNo: 885012006042; E-mail: libraries@we-online.com
footprint WCAP-CSGP 0603, H=0.8mm
pins: 1, 2

## WCAP-CSGP 0603, 885012006043
designator C?, comment 680 pF
WCAP-CSGP MLCC, NP0, 0603, 680 pF,25Vdc; Manufacturer: Wurth Elektronik; partNo: 885012006043; E-mail: libraries@we-online.com
footprint WCAP-CSGP 0603, H=0.8mm
pins: 1, 2

## WCAP-CSGP 0603, 885012006044
designator C?, comment 1000 pF
WCAP-CSGP MLCC, NP0, 0603, 1000 pF,25Vdc; Manufacturer: Wurth Elektronik; partNo: 885012006044; E-mail: libraries@we-online.com
footprint WCAP-CSGP 0603, H=0.8mm
pins: 1, 2

## WCAP-CSGP 0603, 885012006045
designator C?, comment 1 pF
WCAP-CSGP MLCC, NP0, 0603, 1 pF,50Vdc; Manufacturer: Wurth Elektronik; partNo: 885012006045; E-mail: libraries@we-online.com
footprint WCAP-CSGP 0603, H=0.8mm
pins: 1, 2

## WCAP-CSGP 0603, 885012006046
designator C?, comment 1.5 pF
WCAP-CSGP MLCC, NP0, 0603, 1.5 pF,50Vdc; Manufacturer: Wurth Elektronik; partNo: 885012006046; E-mail: libraries@we-online.com
footprint WCAP-CSGP 0603, H=0.8mm
pins: 1, 2

## WCAP-CSGP 0603, 885012006047
designator C?, comment 2.2 pF
WCAP-CSGP MLCC, NP0, 0603, 2.2 pF,50Vdc; Manufacturer: Wurth Elektronik; partNo: 885012006047; E-mail: libraries@we-online.com
footprint WCAP-CSGP 0603, H=0.8mm
pins: 1, 2

## WCAP-CSGP 0603, 885012006048
designator C?, comment 3.3 pF
WCAP-CSGP MLCC, NP0, 0603, 3.3 pF,50Vdc; Manufacturer: Wurth Elektronik; partNo: 885012006048; E-mail: libraries@we-online.com
footprint WCAP-CSGP 0603, H=0.8mm
pins: 1, 2

## WCAP-CSGP 0603, 885012006049
designator C?, comment 4.7 pF
WCAP-CSGP MLCC, NP0, 0603, 4.7 pF,50Vdc; Manufacturer: Wurth Elektronik; partNo: 885012006049; E-mail: libraries@we-online.com
footprint WCAP-CSGP 0603, H=0.8mm
pins: 1, 2

## WCAP-CSGP 0603, 885012006050
designator C?, comment 6.8 pF
WCAP-CSGP MLCC, NP0, 0603, 6.8 pF,50Vdc; Manufacturer: Wurth Elektronik; partNo: 885012006050; E-mail: libraries@we-online.com
footprint WCAP-CSGP 0603, H=0.8mm
pins: 1, 2

## WCAP-CSGP 0603, 885012006051
designator C?, comment 10 pF
WCAP-CSGP MLCC, NP0, 0603, 10 pF,50Vdc; Manufacturer: Wurth Elektronik; partNo: 885012006051; E-mail: libraries@we-online.com
footprint WCAP-CSGP 0603, H=0.8mm
pins: 1, 2

## WCAP-CSGP 0603, 885012006052
designator C?, comment 15 pF
WCAP-CSGP MLCC, NP0, 0603, 15 pF,50Vdc; Manufacturer: Wurth Elektronik; partNo: 885012006052; E-mail: libraries@we-online.com
footprint WCAP-CSGP 0603, H=0.8mm
pins: 1, 2

## WCAP-CSGP 0603, 885012006053
designator C?, comment 22 pF
WCAP-CSGP MLCC, NP0, 0603, 22 pF,50Vdc; Manufacturer: Wurth Elektronik; partNo: 885012006053; E-mail: libraries@we-online.com
footprint WCAP-CSGP 0603, H=0.8mm
pins: 1, 2

## WCAP-CSGP 0603, 885012006054
designator C?, comment 33 pF
WCAP-CSGP MLCC, NP0, 0603, 33 pF,50Vdc; Manufacturer: Wurth Elektronik; partNo: 885012006054; E-mail: libraries@we-online.com
footprint WCAP-CSGP 0603, H=0.8mm
pins: 1, 2

## WCAP-CSGP 0603, 885012006055
designator C?, comment 47 pF
WCAP-CSGP MLCC, NP0, 0603, 47 pF,50Vdc; Manufacturer: Wurth Elektronik; partNo: 885012006055; E-mail: libraries@we-online.com
footprint WCAP-CSGP 0603, H=0.8mm
pins: 1, 2

## WCAP-CSGP 0603, 885012006056
designator C?, comment 68 pF
WCAP-CSGP MLCC, NP0, 0603, 68 pF,50Vdc; Manufacturer: Wurth Elektronik; partNo: 885012006056; E-mail: libraries@we-online.com
footprint WCAP-CSGP 0603, H=0.8mm
pins: 1, 2

## WCAP-CSGP 0603, 885012006057
designator C?, comment 100 pF
WCAP-CSGP MLCC, NP0, 0603, 100 pF,50Vdc; Manufacturer: Wurth Elektronik; partNo: 885012006057; E-mail: libraries@we-online.com
footprint WCAP-CSGP 0603, H=0.8mm
pins: 1, 2

## WCAP-CSGP 0603, 885012006058
designator C?, comment 150 pF
WCAP-CSGP MLCC, NP0, 0603, 150 pF,50Vdc; Manufacturer: Wurth Elektronik; partNo: 885012006058; E-mail: libraries@we-online.com
footprint WCAP-CSGP 0603, H=0.8mm
pins: 1, 2

## WCAP-CSGP 0603, 885012006059
designator C?, comment 220 pF
WCAP-CSGP MLCC, NP0, 0603, 220 pF,50Vdc; Manufacturer: Wurth Elektronik; partNo: 885012006059; E-mail: libraries@we-online.com
footprint WCAP-CSGP 0603, H=0.8mm
pins: 1, 2

## WCAP-CSGP 0603, 885012006060
designator C?, comment 330 pF
WCAP-CSGP MLCC, NP0, 0603, 330 pF,50Vdc; Manufacturer: Wurth Elektronik; partNo: 885012006060; E-mail: libraries@we-online.com
footprint WCAP-CSGP 0603, H=0.8mm
pins: 1, 2

## WCAP-CSGP 0603, 885012006061
designator C?, comment 470 pF
WCAP-CSGP MLCC, NP0, 0603, 470 pF,50Vdc; Manufacturer: Wurth Elektronik; partNo: 885012006061; E-mail: libraries@we-online.com
footprint WCAP-CSGP 0603, H=0.8mm
pins: 1, 2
